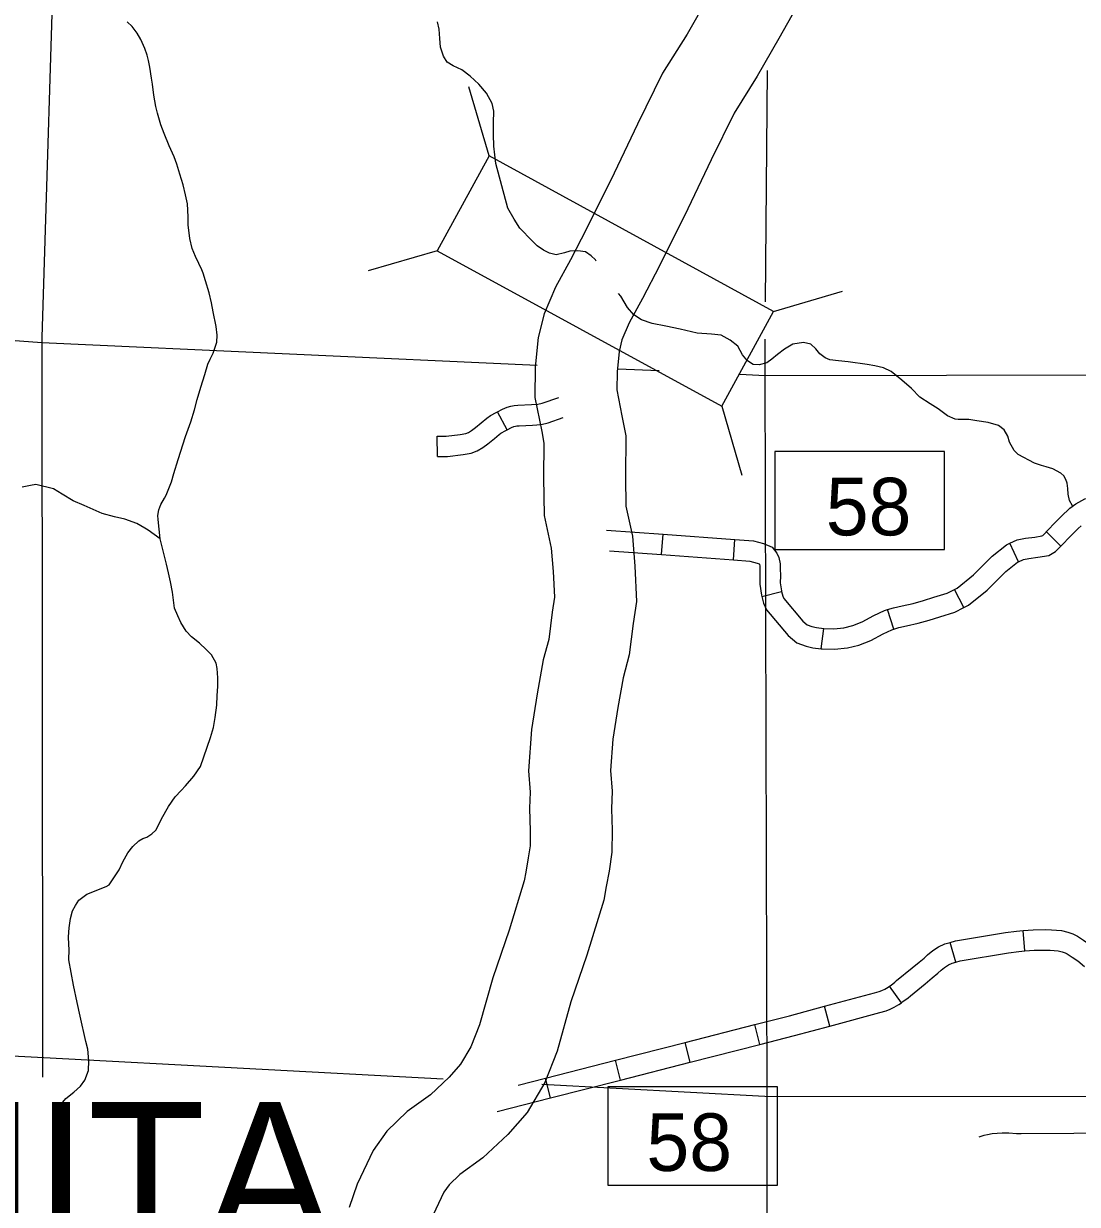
# Model space of a CAD drawing. Extents: x -492261 to -432772, y 1441225 to 1452922.
# Drawn here: x -463644.7 to -463423.9, y 1451467.4 to 1451714.7 of the extents above; entities that cross this region are included whole.
import ezdxf

# ---------------------------------------------------------------- set-up
doc = ezdxf.new("R2010")
doc.units = 0
doc.layers.add('Default', color=7, linetype='Continuous')

msp = doc.modelspace()

# ---------------------------------------------------------------- linework, layer by layer
at = {"layer": 'Default'}
for p, q in [((-463547.15, 1451687.01), (-463551.39, 1451701.49)), ((-463558.01, 1451667.16), (-463572.49, 1451662.92)), ((-463487.59, 1451654.43), (-463473.12, 1451658.67)), ((-463498.45, 1451634.58), (-463494.21, 1451620.1)), ((-463543.41, 1451629.61), (-463545.41, 1451633.4)), ((-463557.94, 1451624.01), (-463558.02, 1451628.3)), ((-463511.02, 1451603.49), (-463510.71, 1451607.77)), ((-463427.38, 1451605.29), (-463430.45, 1451608.28)), ((-463495.98, 1451602.39), (-463495.66, 1451606.66)), ((-463436.27, 1451602.01), (-463438.08, 1451605.89)), ((-463490.06, 1451594.7), (-463485.91, 1451595.78)), ((-463447.7, 1451592.4), (-463449.67, 1451596.2)), ((-463462.41, 1451587.88), (-463463.73, 1451591.96)), ((-463477.58, 1451583.78), (-463477.08, 1451588.03)), ((-463434.93, 1451520.48), (-463435.27, 1451524.75)), ((-463449.41, 1451518.13), (-463450.56, 1451522.26)), ((-463460.81, 1451509.6), (-463463.29, 1451513.09)), ((-463475.81, 1451504.73), (-463476.93, 1451508.87)), ((-463490.43, 1451500.88), (-463491.49, 1451505.03)), ((-463505.04, 1451497.14), (-463506.1, 1451501.29)), ((-463519.66, 1451493.4), (-463520.72, 1451497.55)), ((-463534.27, 1451489.66), (-463535.33, 1451493.82))]:
    msp.add_line(p, q, dxfattribs=at)
for points in [[(-463637.99, 1451741.6), (-463640.85, 1451648.99), (-463640.73, 1451498.55), (-463640.72, 1451494.02)], [(-463501.4, 1451720.06), (-463505.71, 1451712.5), (-463510.82, 1451704.32), (-463516.06, 1451693.66), (-463520.97, 1451683.42), (-463526.74, 1451671.72), (-463530.14, 1451665.25), (-463533.28, 1451659.51), (-463535.65, 1451653.92), (-463536.88, 1451649), (-463537.5, 1451642.74), (-463537.57, 1451636.38), (-463536.15, 1451629.31), (-463535.69, 1451626.86), (-463535.75, 1451619.64), (-463535.63, 1451611.65), (-463534.14, 1451604.85), (-463533.75, 1451599.95), (-463533.48, 1451594.6), (-463533.98, 1451591.46), (-463534.67, 1451585.72), (-463535.81, 1451581.44), (-463537.09, 1451574.33), (-463538.31, 1451566.83), (-463538.9, 1451558.2), (-463538.55, 1451553.72), (-463538.72, 1451550.34), (-463538.54, 1451545.57), (-463538.59, 1451542.49), (-463538.95, 1451539.94), (-463539.5, 1451536.98), (-463539.82, 1451535.13), (-463542.99, 1451524.85), (-463546.4, 1451514.85), (-463549.15, 1451504.99), (-463550.97, 1451500.41), (-463553.13, 1451496.73), (-463555.56, 1451493.99), (-463559.46, 1451490.33), (-463564.31, 1451486.81), (-463568.56, 1451482.7), (-463571.45, 1451478.64), (-463574.79, 1451471.63), (-463576.47, 1451466.71)], [(-463482.84, 1451718.02), (-463486.5, 1451711.58), (-463490.99, 1451703.7), (-463495.82, 1451695.98), (-463500.64, 1451686.17), (-463505.56, 1451675.93), (-463511.46, 1451663.95), (-463515.03, 1451657.15), (-463517.83, 1451652.03), (-463519.35, 1451648.46), (-463519.95, 1451646.06), (-463520.36, 1451641.8), (-463520.41, 1451637.98), (-463519.33, 1451632.58), (-463518.54, 1451628.39), (-463518.61, 1451619.71), (-463518.51, 1451613.63), (-463517.15, 1451607.38), (-463516.64, 1451601.07), (-463516.27, 1451593.68), (-463517, 1451589.09), (-463517.8, 1451582.47), (-463519.06, 1451577.71), (-463520.19, 1451571.44), (-463521.26, 1451564.86), (-463521.71, 1451558.28), (-463521.38, 1451553.96), (-463521.56, 1451550.23), (-463521.4, 1451545.74), (-463521.47, 1451541.16), (-463522.03, 1451537.18), (-463522.62, 1451533.97), (-463523.11, 1451531.13), (-463526.69, 1451519.56), (-463530.02, 1451509.77), (-463532.88, 1451499.5), (-463535.52, 1451492.87), (-463539.19, 1451486.6), (-463543.27, 1451482.02), (-463548.51, 1451477.1), (-463553.26, 1451473.64), (-463555.52, 1451471.46), (-463556.62, 1451469.91), (-463558.89, 1451465.15)], [(-463621.8, 1451542.31), (-463620.55, 1451543.53), (-463619.7, 1451544), (-463618.85, 1451544.29), (-463617.78, 1451544.99), (-463616.98, 1451545.74), (-463616.43, 1451546.78), (-463615.81, 1451548.16), (-463614.3, 1451550.69), (-463612.95, 1451552.77), (-463611.65, 1451554.1), (-463610.75, 1451555.08), (-463609, 1451557.05), (-463607.6, 1451559.12), (-463605.55, 1451565.21), (-463604.89, 1451567.28), (-463604.51, 1451569.34), (-463604.2, 1451571.92), (-463604.1, 1451573.98), (-463604.01, 1451575.87), (-463603.97, 1451577.7), (-463604.11, 1451579.64), (-463604.35, 1451580.78), (-463605.33, 1451582.49), (-463606.43, 1451583.62), (-463607.81, 1451584.92), (-463609.48, 1451586.28), (-463610.63, 1451587.46), (-463611.73, 1451589.28), (-463612.38, 1451590.65), (-463613.08, 1451592.3), (-463613.51, 1451595.61), (-463613.93, 1451597.78), (-463614.35, 1451599.67), (-463614.71, 1451601.49), (-463616.08, 1451606.8), (-463616.47, 1451610.85), (-463616.53, 1451611.71), (-463616.37, 1451612.86), (-463615.93, 1451614.01), (-463615.14, 1451615.33), (-463614.81, 1451615.97), (-463613.7, 1451618.72), (-463613.2, 1451620.45), (-463612.26, 1451623.43), (-463610.77, 1451628.25), (-463609.66, 1451631.3), (-463608.89, 1451633.82), (-463608.29, 1451636.01), (-463607.51, 1451638.59), (-463606.74, 1451641.23), (-463606.08, 1451643.35), (-463605.58, 1451644.45), (-463604.97, 1451645.71), (-463604.63, 1451646.75), (-463604.19, 1451648.01), (-463604.09, 1451649.44), (-463604.34, 1451651.27), (-463604.94, 1451654.35), (-463605.3, 1451656.24), (-463605.78, 1451658.35), (-463606.55, 1451660.85), (-463607.02, 1451662.45), (-463607.31, 1451663.13), (-463607.96, 1451664.5), (-463608.66, 1451665.92), (-463609.36, 1451667.63), (-463609.83, 1451669.69), (-463610.21, 1451672.6), (-463610.22, 1451674.2), (-463610.3, 1451675.63), (-463610.37, 1451677), (-463610.73, 1451678.83), (-463611.26, 1451680.94), (-463611.92, 1451683.22), (-463612.56, 1451685.27), (-463613.15, 1451686.81), (-463614.2, 1451689.14), (-463615.25, 1451691.71), (-463615.9, 1451693.53), (-463616.61, 1451695.93), (-463616.97, 1451697.35), (-463617.39, 1451699.75), (-463617.64, 1451702.04), (-463617.88, 1451703.29), (-463618.25, 1451705.63), (-463618.49, 1451707), (-463618.79, 1451708.14), (-463619.26, 1451709.51), (-463620.14, 1451711.39), (-463620.89, 1451712.75), (-463621.93, 1451714.12), (-463622.97, 1451715.13)], [(-463524.73, 1451664.94), (-463524.87, 1451665.21), (-463525.79, 1451666.06), (-463526.99, 1451666.91), (-463528.59, 1451667.12), (-463530.25, 1451667.04), (-463531.38, 1451666.74), (-463533.09, 1451666.27), (-463534.52, 1451666.65), (-463535.78, 1451667.26), (-463537.1, 1451668.17), (-463538.14, 1451669.24), (-463540.73, 1451671.84), (-463541.89, 1451673.77), (-463543.23, 1451676.05), (-463545.72, 1451685.4), (-463546.16, 1451689.06), (-463546.24, 1451691.52), (-463546.21, 1451693.92), (-463546.18, 1451696.38), (-463546.54, 1451697.98), (-463547.7, 1451700.14), (-463549.32, 1451702.07), (-463551.1, 1451703.71), (-463552.88, 1451705.06), (-463554.66, 1451705.9), (-463555.92, 1451706.63), (-463556.74, 1451707.88), (-463557.33, 1451709.76), (-463557.46, 1451711.59), (-463557.65, 1451713.53), (-463557.95, 1451715.13)], [(-463488.92, 1451704.9), (-463489.32, 1451656.47)], [(-463537.11, 1451643.12), (-463640.85, 1451647.85), (-463793.35, 1451659.21), (-463942.76, 1451667.26), (-464094.29, 1451673.71), (-464247.02, 1451675.18)], [(-463446.67, 1451631.78), (-463447.86, 1451631.76), (-463448.95, 1451631.81), (-463449.52, 1451631.86), (-463451.12, 1451632.58), (-463453.08, 1451634.05), (-463454.8, 1451635.06), (-463456.98, 1451636.46), (-463458.71, 1451638.28), (-463460.73, 1451640.03), (-463462.97, 1451641.83), (-463464.57, 1451642.61), (-463466.4, 1451643.05), (-463467.95, 1451643.32), (-463471.94, 1451643.9), (-463474, 1451644.05), (-463475.77, 1451644.26), (-463476.74, 1451644.71), (-463477.89, 1451645.55), (-463478.76, 1451646.57), (-463479.8, 1451647.59), (-463481.34, 1451647.92), (-463483.56, 1451647.55), (-463485.26, 1451646.56), (-463486.73, 1451645.39), (-463487.92, 1451644.41), (-463488.99, 1451643.65), (-463490.59, 1451643.23), (-463491.84, 1451643.33), (-463493.05, 1451644.06), (-463494.09, 1451645.37), (-463495.08, 1451647.13), (-463496.69, 1451648.43), (-463498.58, 1451649.49), (-463500.58, 1451649.64), (-463503.55, 1451649.9), (-463507.15, 1451650.71), (-463510.12, 1451651.31), (-463512.98, 1451651.9), (-463515.27, 1451652.68), (-463516.88, 1451653.75), (-463518.15, 1451655.28), (-463519.6, 1451657.61), (-463520.09, 1451658.21)], [(-463489.38, 1451648.59), (-463489.44, 1451641.74), (-463488.97, 1451490.05), (-463489, 1451447.14)], [(-463511.55, 1451641.96), (-463520.2, 1451642.35)], [(-463337.5, 1451641.25), (-463489.32, 1451640.94), (-463494.68, 1451641.19)], [(-463545.41, 1451633.4), (-463544.33, 1451633.97), (-463543.38, 1451634.4), (-463542.61, 1451634.59), (-463541.94, 1451634.73), (-463541.12, 1451634.78), (-463538.3, 1451634.9), (-463536.94, 1451635), (-463536.02, 1451635.23), (-463532.57, 1451636.43)], [(-463558.02, 1451628.3), (-463556.17, 1451628.33), (-463553.23, 1451628.67), (-463552.05, 1451628.88), (-463551.51, 1451629.09), (-463550.87, 1451629.46), (-463550.04, 1451630.1), (-463548.82, 1451631.07), (-463547.65, 1451632.1), (-463546.89, 1451632.6), (-463545.7, 1451633.25), (-463545.41, 1451633.4)], [(-463543.41, 1451629.61), (-463542.45, 1451630.12), (-463541.98, 1451630.33), (-463541.66, 1451630.41), (-463541.37, 1451630.47), (-463540.89, 1451630.5), (-463538.06, 1451630.62), (-463536.26, 1451630.75), (-463534.79, 1451631.11), (-463531.64, 1451632.22)], [(-463424.99, 1451613.7), (-463425.61, 1451614.79), (-463425.86, 1451616.16), (-463425.98, 1451617.31), (-463426.11, 1451618.45), (-463426.34, 1451619.19), (-463426.81, 1451619.99), (-463427.44, 1451620.55), (-463429.11, 1451621.45), (-463430.48, 1451621.89), (-463431.45, 1451622.17), (-463432.94, 1451622.61), (-463436.38, 1451624.45), (-463437.19, 1451625.3), (-463438.18, 1451627.01), (-463438.53, 1451628.32), (-463439.29, 1451629.63), (-463440.49, 1451630.53), (-463442.61, 1451631.14), (-463445.01, 1451631.51), (-463446.67, 1451631.78)], [(-463557.94, 1451624.01), (-463555.88, 1451624.05), (-463552.61, 1451624.43), (-463550.92, 1451624.73), (-463549.65, 1451625.21), (-463548.47, 1451625.9), (-463547.41, 1451626.72), (-463546.06, 1451627.78), (-463545.04, 1451628.68), (-463544.68, 1451628.92), (-463543.66, 1451629.48), (-463543.41, 1451629.61)], [(-463487.35, 1451604.57), (-463451.78, 1451604.57), (-463451.78, 1451625.12), (-463487.35, 1451625.12), (-463487.35, 1451604.57)], [(-463616.08, 1451606.8), (-463618.55, 1451608.6), (-463619.3, 1451609.05), (-463620.96, 1451610), (-463623.48, 1451610.89), (-463625.65, 1451611.38), (-463628.23, 1451612.09), (-463632.01, 1451613.77), (-463634.3, 1451614.77), (-463636.6, 1451616.18), (-463638.38, 1451617.24), (-463642.09, 1451618.17), (-463643.23, 1451617.99), (-463645, 1451617.63)], [(-463426.08, 1451612.69), (-463425.52, 1451613.2), (-463424.29, 1451614.12), (-463422.38, 1451615.14), (-463420.77, 1451615.54), (-463418.9, 1451615.31), (-463415.57, 1451614.36), (-463414.66, 1451614.03), (-463414.62, 1451614.27), (-463414.59, 1451614.81)], [(-463438.08, 1451605.89), (-463436.53, 1451606.61), (-463434.78, 1451606.92), (-463432.84, 1451607.17), (-463431.39, 1451607.4), (-463431.19, 1451607.52), (-463429.94, 1451608.8), (-463428.9, 1451609.92), (-463427.98, 1451610.81), (-463426.78, 1451612.04), (-463426.08, 1451612.69)], [(-463436.27, 1451602.01), (-463435.24, 1451602.49), (-463434.15, 1451602.68), (-463432.22, 1451602.93), (-463429.91, 1451603.3), (-463428.52, 1451604.12), (-463426.83, 1451605.85), (-463425.84, 1451606.92), (-463424.96, 1451607.77), (-463423.79, 1451608.97), (-463423.17, 1451609.54)], [(-463522.54, 1451608.63), (-463510.71, 1451607.77)], [(-463510.71, 1451607.77), (-463495.66, 1451606.66)], [(-463495.66, 1451606.66), (-463491.82, 1451606.38), (-463489.66, 1451605.8), (-463487.91, 1451605.08), (-463486.92, 1451603.78), (-463486.47, 1451602.9), (-463486.18, 1451601.56), (-463486.17, 1451600.55), (-463486.16, 1451599.02), (-463486.2, 1451597.57), (-463485.93, 1451595.87), (-463485.91, 1451595.78)], [(-463449.67, 1451596.2), (-463449.11, 1451596.49), (-463445.7, 1451599.24), (-463441.79, 1451603.18), (-463438.78, 1451605.57), (-463438.08, 1451605.89)], [(-463521.92, 1451604.29), (-463511.02, 1451603.49)], [(-463511.02, 1451603.49), (-463495.98, 1451602.39)], [(-463495.98, 1451602.39), (-463492.54, 1451602.13), (-463491.03, 1451601.73), (-463490.61, 1451601.55), (-463490.56, 1451601.49), (-463490.54, 1451601.46), (-463490.47, 1451601.09), (-463490.46, 1451600.5), (-463490.44, 1451599.05), (-463490.49, 1451597.3), (-463490.14, 1451595), (-463490.06, 1451594.7)], [(-463447.7, 1451592.4), (-463446.76, 1451592.88), (-463442.82, 1451596.05), (-463438.93, 1451599.98), (-463436.51, 1451601.89), (-463436.27, 1451602.01)], [(-463490.06, 1451594.7), (-463489.7, 1451593.32), (-463489.03, 1451591.93), (-463484.53, 1451586.54), (-463482.7, 1451584.98), (-463480.78, 1451584.31), (-463479.35, 1451583.98), (-463477.58, 1451583.78)], [(-463485.91, 1451595.78), (-463485.66, 1451594.81), (-463485.4, 1451594.27), (-463481.47, 1451589.56), (-463480.53, 1451588.76), (-463479.59, 1451588.43), (-463478.62, 1451588.21), (-463477.08, 1451588.03)], [(-463463.73, 1451591.96), (-463462.47, 1451592.37), (-463460.67, 1451592.75), (-463458.34, 1451593.28), (-463456.21, 1451593.85), (-463454.02, 1451594.56), (-463451.24, 1451595.4), (-463449.67, 1451596.2)], [(-463462.41, 1451587.88), (-463461.36, 1451588.22), (-463459.75, 1451588.57), (-463457.31, 1451589.12), (-463455, 1451589.74), (-463452.75, 1451590.46), (-463449.62, 1451591.41), (-463447.7, 1451592.4)], [(-463477.08, 1451588.03), (-463477.05, 1451588.03), (-463474.95, 1451587.95), (-463472.86, 1451588.17), (-463471.01, 1451588.65), (-463469, 1451589.38), (-463466.58, 1451590.74), (-463464.35, 1451591.76), (-463463.73, 1451591.96)], [(-463477.58, 1451583.78), (-463477.38, 1451583.75), (-463474.8, 1451583.65), (-463472.1, 1451583.94), (-463469.74, 1451584.55), (-463467.21, 1451585.47), (-463464.64, 1451586.91), (-463462.79, 1451587.76), (-463462.41, 1451587.88)], [(-463635.08, 1451465.56), (-463635.11, 1451468.13), (-463635.13, 1451469.62), (-463635.25, 1451470.93), (-463635.73, 1451472.93), (-463636.38, 1451474.47), (-463637.02, 1451476.23), (-463637.61, 1451477.89), (-463638.15, 1451480.91), (-463638.11, 1451482.11), (-463638.18, 1451483.54), (-463638.02, 1451484.69), (-463637.8, 1451485.66), (-463637.64, 1451486.35), (-463637.31, 1451487.39), (-463636.81, 1451488.36), (-463635.79, 1451489.58), (-463634.15, 1451490.85), (-463632.74, 1451492.13), (-463631.84, 1451493.4), (-463631.06, 1451495.41), (-463630.97, 1451497.41), (-463631.22, 1451499.87), (-463631.64, 1451501.47), (-463632.83, 1451506.83), (-463633.43, 1451509.63), (-463634.21, 1451513.28), (-463635.18, 1451518.59), (-463635.09, 1451520.77), (-463635.21, 1451521.79), (-463635.29, 1451523.39), (-463635.14, 1451525.28), (-463634.87, 1451527.29), (-463634.43, 1451528.9), (-463633.82, 1451529.99), (-463633.09, 1451531.09), (-463631.39, 1451532.36), (-463627.36, 1451533.95), (-463626.73, 1451534.3), (-463624.66, 1451537.47), (-463623.87, 1451539.14), (-463622.81, 1451540.99), (-463621.8, 1451542.31)], [(-463450.56, 1451522.26), (-463449.45, 1451522.57), (-463439.01, 1451524.31), (-463436.69, 1451524.64), (-463435.27, 1451524.75)], [(-463435.27, 1451524.75), (-463433.19, 1451524.91), (-463430.62, 1451524.94), (-463429.38, 1451524.89), (-463427.27, 1451524.73), (-463425.94, 1451524.39), (-463424.87, 1451524.05), (-463423.91, 1451523.58), (-463422.64, 1451522.71), (-463421.31, 1451521.82), (-463419.76, 1451520.57)], [(-463556.78, 1451493.58), (-463640.44, 1451498.04), (-463793.68, 1451506.14), (-463942.87, 1451515.91), (-464056.58, 1451522.01)], [(-463463.29, 1451513.09), (-463462.98, 1451513.32), (-463462.17, 1451513.9), (-463461.81, 1451514.27), (-463458.56, 1451516.89), (-463457.09, 1451518.1), (-463456.05, 1451518.96), (-463455.35, 1451519.68), (-463454.24, 1451520.53), (-463453.04, 1451521.29), (-463451.68, 1451521.95), (-463450.56, 1451522.26)], [(-463449.41, 1451518.13), (-463448.52, 1451518.38), (-463438.36, 1451520.07), (-463436.23, 1451520.37), (-463434.93, 1451520.48)], [(-463434.93, 1451520.48), (-463433, 1451520.63), (-463430.67, 1451520.66), (-463429.63, 1451520.62), (-463427.97, 1451520.48), (-463427.12, 1451520.27), (-463426.48, 1451520.06), (-463426.07, 1451519.86), (-463425.04, 1451519.16), (-463423.84, 1451518.36), (-463422.45, 1451517.23)], [(-463460.81, 1451509.6), (-463460.48, 1451509.84), (-463459.36, 1451510.65), (-463458.92, 1451511.09), (-463455.84, 1451513.57), (-463454.37, 1451514.8), (-463453.15, 1451515.8), (-463452.49, 1451516.47), (-463451.79, 1451517.01), (-463450.95, 1451517.54), (-463450.16, 1451517.93), (-463449.41, 1451518.13)], [(-463476.93, 1451508.87), (-463466.42, 1451511.71), (-463465.43, 1451511.97), (-463464.94, 1451512.19), (-463464.29, 1451512.49), (-463463.6, 1451512.87), (-463463.29, 1451513.09)], [(-463491.49, 1451505.03), (-463484.27, 1451506.88), (-463476.93, 1451508.87)], [(-463475.81, 1451504.73), (-463465.32, 1451507.57), (-463464.03, 1451507.91), (-463463.16, 1451508.28), (-463462.33, 1451508.68), (-463461.32, 1451509.23), (-463460.81, 1451509.6)], [(-463506.1, 1451501.29), (-463491.49, 1451505.03)], [(-463490.43, 1451500.88), (-463483.18, 1451502.73), (-463475.81, 1451504.73)], [(-463520.72, 1451497.55), (-463506.1, 1451501.29)], [(-463505.04, 1451497.14), (-463490.43, 1451500.88)], [(-463535.33, 1451493.82), (-463520.72, 1451497.55)], [(-463519.66, 1451493.4), (-463505.04, 1451497.14)], [(-463541.11, 1451492.34), (-463535.33, 1451493.82)], [(-463534.27, 1451489.66), (-463519.66, 1451493.4)], [(-463336.18, 1451489.83), (-463489.43, 1451489.99), (-463536.15, 1451492.48)], [(-463522.33, 1451471.42), (-463486.76, 1451471.42), (-463486.76, 1451491.97), (-463522.33, 1451491.97), (-463522.33, 1451471.42)], [(-463545.48, 1451486.8), (-463534.27, 1451489.66)], [(-463435.7, 1451482.12), (-463436.7, 1451482.18), (-463438.33, 1451482.29), (-463439.68, 1451482.29), (-463441.82, 1451482.12), (-463442.74, 1451481.93), (-463443.55, 1451481.78), (-463444.6, 1451481.44)], [(-463385.68, 1451482.4), (-463396.23, 1451482.34), (-463413.63, 1451482.26), (-463435.7, 1451482.12)]]:
    msp.add_lwpolyline(points, dxfattribs=at)
for points in [[(-463558.01, 1451667.16), (-463498.45, 1451634.58), (-463487.59, 1451654.43), (-463547.15, 1451687.01)], [(-463487.35, 1451604.57), (-463451.78, 1451604.57), (-463451.78, 1451625.12), (-463487.35, 1451625.12)], [(-463522.33, 1451471.42), (-463486.76, 1451471.42), (-463486.76, 1451491.97), (-463522.33, 1451491.97)]]:
    msp.add_lwpolyline(points, close=True, dxfattribs=at)

# ---------------------------------------------------------------- texts
for s, height, p in [('58', 12.057, (-463476.64, 1451607.52)), ('WASHITA', 30.171, (-463763.5, 1451458.66)), ('58', 12.057, (-463514.21, 1451474.37))]:
    msp.add_text(s, height=height, dxfattribs=at).set_placement(p)

doc.saveas('drawing.dxf')
